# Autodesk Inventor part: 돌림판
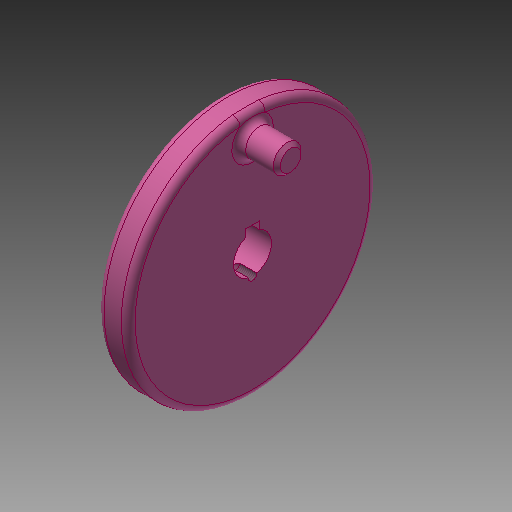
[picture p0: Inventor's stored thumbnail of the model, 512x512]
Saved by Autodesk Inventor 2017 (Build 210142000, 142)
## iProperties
Created: 2019-09
Part Number: 돌림판
Material: 알루미늄 6061
Document SubType Name: Modeling
Designer: mduedu
Density: 2.71 g/cm^3
Mass: 83.7217 g
Surface Area: 107.333 cm^2
Volume: 30.8936 cm^3
Appearance: 분홍색
Author: mduedu
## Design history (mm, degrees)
sketch "스케치1"
  geometry: L1 (0, 0)-(9, 0); L2 (9, 0)-(9, 36); L3 (9, 36)-(0, 36); L4 (0, 23)-(4, 23); L5 (4, 23)-(4, 10); L6 (4, 10)-(0, 10); L7 (0, 36)-(0, 23); L8 (0, 10)-(0, 0)
  constraints: 16 end point, 4 parallel, 2 horizontal, 2 perpendicular, 1 collinear
  dimensions: "d0" = 72 diameter of L3 L1; "d2" = 9 distance of L2.end L3.end; "d3" = 4 distance between parallel lines of L7 L5; "d4" = 20 diameter of L6 L1; "d5" = 46 diameter of L4 L1
revolve "회전1" sketch "스케치1" stored, may be unused: angle "d6" = 90 deg
fillet "모깎기1" dims "d7" = 3
sketch "스케치2"
  geometry: C1 r 4 at (0, 29); 1 further point
  constraints: 1 centre point, 1 vertical alignment
  dimensions: "d8" = 8 diameter of C1; "d9" = 29 distance of C1.centre point (0, 0)
extrude "돌출1" join sketch "스케치2" distance "d10" = 11; taper "d11" = 0 deg
fillet "모깎기2" dims "d12" = 2
fillet "모깎기3" dims "d13" = 2
chamfer "모따기1" distance "d14" = 1; stored, may be unused: second distance "d15" = 2, angle "d16" = 45 deg
sketch "스케치3"
  geometry: L1 (-2, 5.123)-(2, 5.123); L2 (2, 5.123)-(2, 7.3); L3 (2, 7.3)-(-2, 7.3); L4 (-2, 7.3)-(-2, 5.123); A1 r 5.5 centre (0, 0) between (-2, 5.123) and (2, 5.123); 1 further point
  constraints: 8 end point, 2 parallel, 2 point on circle, 1 centre point, 1 coincident, 1 horizontal, 1 perpendicular
  dimensions: "d17" = 11 diameter of A1; "d18" = 4 distance of L2.end L3.end; "d19" = 12.8 dimension on A1 L3
extrude "돌출2" cut sketch "스케치3" stored distance "d20" = 11; taper "d21" = 0 deg
chamfer "모따기2" distance "d22" = 0.5; stored, may be unused: second distance "d23" = 2, angle "d24" = 45 deg
sketch "스케치4"
  geometry: A1 r 5.5 centre (0, 0) between (-2, 5.123) and (2, 5.123) reference; 2 further points
  constraints: 1 point on circle
hole "구멍1" sketch "스케치4" at (0, -5.5) diameter "d25" = 2.459; stored, may be unused: countersink angle "d29" = 90 deg, drill point angle "d31" = 118 deg; dims "d26" = 6, "d27" = 4, "d28" = 2, "d30" = 5
node "솔리드1"
